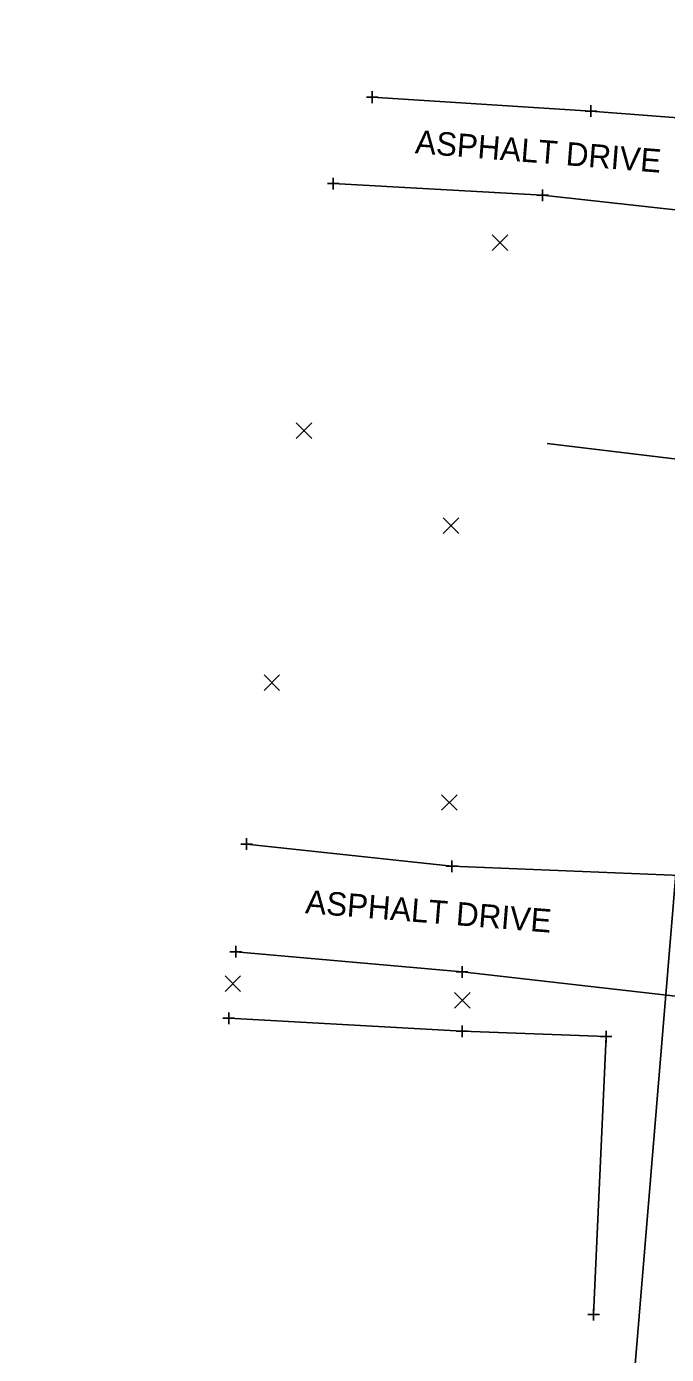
# Model space of a CAD drawing. Extents: x 1380440 to 1381945, y 468756 to 470369.
# Drawn here: x 1381439.7 to 1381494.5, y 468998.9 to 469112.5 of the extents above; entities that cross this region are included whole.
import ezdxf

# ---------------------------------------------------------------- set-up
doc = ezdxf.new("R2010")
doc.units = 0
for name, color, linetype in [('GE_P_Driveway_CL', 7, 'Continuous'), ('GK_Drainage_Nodes', 7, 'Continuous'), ('RW_X_Esmt_SH', 7, 'Continuous'), ('SH_Named_Boundary', 7, 'Continuous'), ('UT_X_Gas', 7, 'Continuous'), ('UT_X_Water', 7, 'Continuous'), ('X-SUBDIVISION', 7, 'Continuous')]:
    doc.layers.add(name, color=color, linetype=linetype)

msp = doc.modelspace()

# ---------------------------------------------------------------- linework, layer by layer
at = {"layer": 'GE_P_Driveway_CL'}
for p, q in [((1381479.57, 469093.38), (1381480.9, 469094.72)), ((1381479.57, 469094.72), (1381480.9, 469093.38)), ((1381462.8, 469077.27), (1381464.13, 469078.61)), ((1381462.8, 469078.61), (1381464.13, 469077.27)), ((1381475.37, 469069.16), (1381476.71, 469070.5)), ((1381475.37, 469070.5), (1381476.71, 469069.16)), ((1381460.04, 469055.72), (1381461.37, 469057.05)), ((1381460.04, 469057.05), (1381461.37, 469055.72)), ((1381475.24, 469045.47), (1381476.57, 469046.8)), ((1381475.24, 469046.8), (1381476.57, 469045.47)), ((1381456.71, 469029.96), (1381458.04, 469031.3)), ((1381456.71, 469031.3), (1381458.04, 469029.96)), ((1381476.36, 469028.54), (1381477.7, 469029.87)), ((1381476.36, 469029.87), (1381477.7, 469028.54))]:
    msp.add_line(p, q, dxfattribs=at)
at = {"layer": 'GK_Drainage_Nodes'}
msp.add_lwpolyline([(1381457.02, 469027.67), (1381476.99, 469026.56), (1381489.32, 469026.11), (1381488.25, 469002.32)], dxfattribs=at)
at = {"layer": 'RW_X_Esmt_SH'}
for points in [[(1381515.44, 469109.41), (1381514.47, 469108.44), (1381509.13, 469105.26), (1381507.75, 469104.81), (1381506.54, 469104.35), (1381504.72, 469104.06), (1381502.21, 469104.2), (1381488.02, 469105.3), (1381469.31, 469106.49)], [(1381465.96, 469099.1), (1381483.88, 469098.09), (1381501.2, 469096.18), (1381506.2, 469094.48), (1381509.67, 469092.51), (1381511.35, 469091.31), (1381512.69, 469089.74), (1381513.05, 469088.48)], [(1381508.96, 469043.74), (1381508.3, 469042.45), (1381505.95, 469040.85), (1381503.53, 469040.25), (1381501.31, 469039.83), (1381497.09, 469039.83), (1381476.12, 469040.68), (1381458.55, 469042.58)], [(1381457.62, 469033.36), (1381476.99, 469031.64), (1381495.52, 469029.54), (1381499.59, 469029.19), (1381501.62, 469028.61), (1381503.96, 469027.52), (1381505.39, 469026.42), (1381506.34, 469025.03), (1381507.02, 469023.6)]]:
    msp.add_lwpolyline(points, dxfattribs=at)
at = {"layer": 'SH_Named_Boundary'}
for p, q in [((1381469.31, 469106.99), (1381469.31, 469105.99)), ((1381468.81, 469106.49), (1381469.81, 469106.49)), ((1381469.31, 469106.49), (1381469.31, 469106.49)), ((1381488.02, 469105.8), (1381488.02, 469104.8)), ((1381487.52, 469105.3), (1381488.52, 469105.3)), ((1381488.02, 469105.3), (1381488.02, 469105.3)), ((1381465.46, 469099.1), (1381466.46, 469099.1)), ((1381465.96, 469099.6), (1381465.96, 469098.6)), ((1381465.96, 469099.1), (1381465.96, 469099.1)), ((1381483.38, 469098.09), (1381484.38, 469098.09)), ((1381483.88, 469098.59), (1381483.88, 469097.59)), ((1381483.88, 469098.09), (1381483.88, 469098.09)), ((1381458.55, 469043.08), (1381458.55, 469042.08)), ((1381458.05, 469042.58), (1381459.05, 469042.58)), ((1381458.55, 469042.58), (1381458.55, 469042.58)), ((1381476.12, 469041.18), (1381476.12, 469040.18)), ((1381475.62, 469040.68), (1381476.62, 469040.68)), ((1381476.12, 469040.68), (1381476.12, 469040.68)), ((1381457.12, 469033.36), (1381458.12, 469033.36)), ((1381457.62, 469033.86), (1381457.62, 469032.86)), ((1381457.62, 469033.36), (1381457.62, 469033.36)), ((1381476.49, 469031.64), (1381477.49, 469031.64)), ((1381476.99, 469032.14), (1381476.99, 469031.14)), ((1381476.99, 469031.64), (1381476.99, 469031.64)), ((1381456.52, 469027.67), (1381457.52, 469027.67)), ((1381457.02, 469028.17), (1381457.02, 469027.17)), ((1381457.02, 469027.67), (1381457.02, 469027.67)), ((1381476.99, 469027.06), (1381476.99, 469026.06)), ((1381476.49, 469026.56), (1381477.49, 469026.56)), ((1381476.99, 469026.56), (1381476.99, 469026.56)), ((1381488.82, 469026.11), (1381489.82, 469026.11)), ((1381489.32, 469026.61), (1381489.32, 469025.61)), ((1381489.32, 469026.11), (1381489.32, 469026.11)), ((1381487.75, 469002.32), (1381488.75, 469002.32)), ((1381488.25, 469002.82), (1381488.25, 469001.82)), ((1381488.25, 469002.32), (1381488.25, 469002.32))]:
    msp.add_line(p, q, dxfattribs=at)
at = {"layer": 'UT_X_Gas'}
msp.add_lwpolyline([(1381485.9, 468926.41), (1381594.27, 470237.89), (1380558, 470279.29)], dxfattribs=at)
at = {"layer": 'UT_X_Water'}
msp.add_line((1381531.94, 469071.17), (1381484.29, 469076.84), dxfattribs=at)

# ---------------------------------------------------------------- texts
at = {"layer": 'X-SUBDIVISION'}
for p in [(1381472.93, 469101.7), (1381463.53, 469036.67)]:
    msp.add_text('ASPHALT DRIVE', height=2, rotation=355.4428, dxfattribs=at).set_placement(p)

doc.saveas('drawing.dxf')
